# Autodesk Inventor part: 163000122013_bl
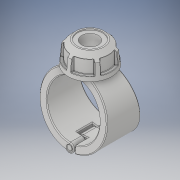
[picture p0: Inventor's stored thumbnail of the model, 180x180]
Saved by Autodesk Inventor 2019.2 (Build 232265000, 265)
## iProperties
Created: 2022-02
Part Number: 163000122013_bl
Material: Generic
Description: Plassadle Threaded 122x1 1/4''
Document SubType Name: Modeling
Designer: comp2
Density: 1 g/cm^3
Appearance: Default
Author: comp2
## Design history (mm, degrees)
derived "16300.ipt"
feature "Solid1::16300.ipt" dims "ScaleForDerivedMember" = 10
feature "Solid2::16300.ipt" dims "ScaleForDerivedMember" = 10
feature "Solid3::16300.ipt" dims "ScaleForDerivedMember" = 10
feature "Solid4::16300.ipt" dims "ScaleForDerivedMember" = 10
tag "TaggingFeature1"
body "Solid1"
body "Solid2"
body "Solid3"
body "Solid4"
other parameters: "d0" = 122 [user parameter], "d2" = 157 [user parameter], "d3" = 61 [user parameter], "d7" = 149.15 [user parameter], "d8" = 85 deg [user parameter], "d9" = 45 deg [user parameter], "d10" = 102 [user parameter], "d11" = 49 [user parameter], "d12" = 35.5495 [user parameter], "d13" = 42.84 [user parameter], "d14" = 58.428 [user parameter], "d42" = 3.5 [user parameter], "d49" = 3.14 [user parameter], "d51" = 0 [user parameter], "d52" = 24.5 [user parameter], "d53" = 86.35 [user parameter], "d54" = 35 [user parameter], "d55" = 0 [user parameter], "d59" = 0 [user parameter], "d61" = 0 [user parameter], "d62" = 35 [user parameter], "d63" = 0 [user parameter], "d65" = 0 [user parameter], "d67" = 0 [user parameter], "d69" = 0 [user parameter], "d70" = 1 [user parameter], "d71" = 96 [user parameter], "d72" = 0 [user parameter], "d73" = 2 [user parameter], "d78" = 86.7 [user parameter], "d79" = 5.1 [user parameter], "d80" = 60 deg [user parameter], "d81" = 5.1 [user parameter], "d84" = 0 [user parameter], "d85" = 1 [user parameter], "d87" = 360 deg [user parameter], "d122" = 61 [user parameter], "d124" = 42.80128 [user parameter], "d125" = 2.53925 [user parameter], "d127" = 207 [user parameter], "d129" = 38.952 [user parameter], "d130" = 33.1092 [user parameter], "d131" = 39.65 [user parameter], "d132" = 45 deg [user parameter], "d133" = 27.755 [user parameter], "d134" = 19.476 [user parameter], "d136" = 0 [user parameter], "d138" = 0 [user parameter], "d" = 122 [user parameter], "d1" = 25 [user parameter], "B" = 157 [user parameter], "E_" = 54 [user parameter], "E1" = 102 [user parameter], "H1" = 207 [user parameter], "H2" = 61 [user parameter], "H3" = 78 [user parameter], "H_costum" = 49 [user parameter], "Rp" = 38.952 [user parameter], "d128" = 50.785 [user parameter]
